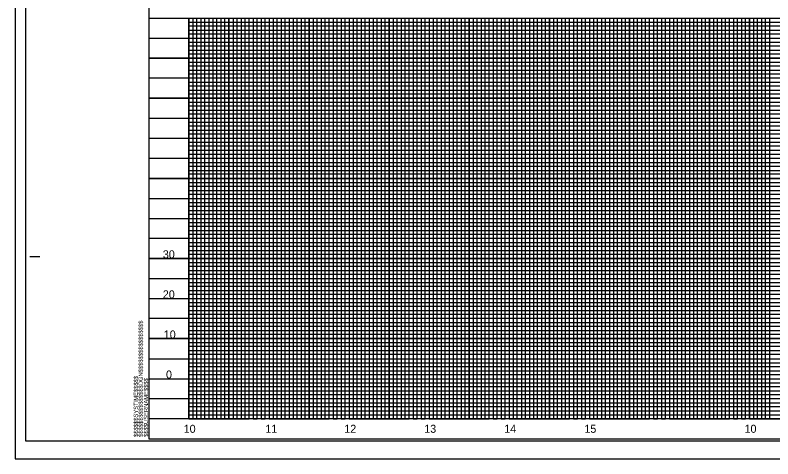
# Model space of a CAD drawing. Extents: x 2180324 to 2182216, y 74532 to 75632.
# Drawn here: x 2180324 to 2181270, y 74532 to 75086 of the extents above; entities that cross this region are included whole.
import ezdxf

# ---------------------------------------------------------------- set-up
doc = ezdxf.new("R2010")
doc.units = 0
for name, color, linetype in [('Exist Structure Minor Culvert Topo', 7, 'Continuous'), ('Old_Level_1', 7, 'Continuous'), ('Old_Level_11', 7, 'Continuous'), ('Old_Level_2', 7, 'Continuous'), ('Old_Level_3', 7, 'Continuous'), ('Scratch_Level_0', 7, 'Continuous'), ('Sheet Border Standard 30in CELL', 7, 'Continuous'), ('Sheet Cutting Line CELL', 7, 'Continuous'), ('Sheet Plot Border Outside CELL', 7, 'Continuous'), ('Sheet Sticker Exception Certification CELL', 7, 'Continuous'), ('Sheet Sticker Incomplete CELL', 7, 'Continuous'), ('Sheet Sticker Preliminary CELL', 7, 'Continuous')]:
    doc.layers.add(name, color=color, linetype=linetype)

msp = doc.modelspace()

# ---------------------------------------------------------------- linework, layer by layer
at = {"layer": 'Exist Structure Minor Culvert Topo'}
for points in [[(2180540.9, 75082.28), (2181240.9, 75082.28), (2181240.9, 74582.28), (2180540.9, 74582.28)], [(2181240.9, 75082.28), (2181940.9, 75082.28), (2181940.9, 74582.28), (2181240.9, 74582.28)]]:
    msp.add_lwpolyline(points, close=True, dxfattribs=at)
at = {"layer": 'Old_Level_11'}
for p, q in [((2180490.9, 75082.28), (2181990.79, 75082.28)), ((2180540.9, 75082.28), (2180540.9, 74582.28)), ((2180590.9, 75082.28), (2180590.9, 74582.28)), ((2180640.9, 75082.28), (2180640.9, 74582.28)), ((2180690.9, 75082.28), (2180690.9, 74582.28)), ((2180740.9, 75082.28), (2180740.9, 74582.28)), ((2180790.9, 75082.28), (2180790.9, 74582.28)), ((2180840.9, 75082.28), (2180840.9, 74582.28)), ((2180890.9, 75082.28), (2180890.9, 74582.28)), ((2180940.9, 75082.28), (2180940.9, 74582.28)), ((2180990.9, 75082.28), (2180990.9, 74582.28)), ((2181040.9, 75082.28), (2181040.9, 74582.28)), ((2181090.9, 75082.28), (2181090.9, 74582.28)), ((2181140.9, 75082.28), (2181140.9, 74582.28)), ((2181190.9, 75082.28), (2181190.9, 74582.28)), ((2181240.9, 75082.28), (2181240.9, 74582.28)), ((2180490.9, 75032.28), (2181990.79, 75032.28)), ((2180490.9, 74982.28), (2181990.79, 74982.28)), ((2180490.9, 74932.28), (2181990.79, 74932.28)), ((2180490.9, 74882.28), (2181990.79, 74882.28)), ((2180490.9, 74832.28), (2181990.79, 74832.28)), ((2180490.9, 74782.28), (2181990.79, 74782.28)), ((2180490.9, 74732.28), (2181990.79, 74732.28)), ((2180490.9, 74682.28), (2181990.79, 74682.28)), ((2180490.9, 74632.28), (2181990.79, 74632.28))]:
    msp.add_line(p, q, dxfattribs=at)
at = {"layer": 'Old_Level_2'}
for points in [[(2180515.9, 75082.28), (2180565.9, 75082.28), (2180565.9, 74582.28), (2180615.9, 74582.28), (2180615.9, 75082.28), (2180665.9, 75082.28), (2180665.9, 74582.28), (2180715.9, 74582.28), (2180715.9, 75082.28), (2180765.9, 75082.28), (2180765.9, 74582.28), (2180815.9, 74582.28), (2180815.9, 75082.28), (2180865.9, 75082.28), (2180865.9, 74582.28), (2180915.9, 74582.28), (2180915.9, 75082.28), (2180965.9, 75082.28), (2180965.9, 74582.28), (2181015.9, 74582.28), (2181015.9, 75082.28), (2181065.9, 75082.28), (2181065.9, 74582.28), (2181115.9, 74582.28), (2181115.9, 74582.28), (2181115.9, 75082.28), (2181165.9, 75082.28), (2181165.9, 74582.28), (2181215.9, 74582.28), (2181215.9, 75082.28), (2181265.9, 75082.28), (2181265.9, 74582.28), (2181315.9, 74582.28)], [(2180490.9, 75057.28), (2181990.9, 75057.28)], [(2181990.9, 75007.28), (2180490.9, 75007.28), (2180490.9, 74957.28), (2181990.9, 74957.28)], [(2181990.9, 74907.28), (2180490.9, 74907.28), (2180490.9, 74857.28), (2181990.9, 74857.28)], [(2181990.9, 74807.28), (2180490.9, 74807.28), (2180490.9, 74757.28), (2181990.9, 74757.28)], [(2181990.9, 74707.28), (2180490.9, 74707.28), (2180490.9, 74657.28), (2181990.9, 74657.28)], [(2181990.9, 74607.28), (2180490.9, 74607.28)]]:
    msp.add_lwpolyline(points, dxfattribs=at)
at = {"layer": 'Scratch_Level_0'}
for p, q in [((2180323.9, 75632.28), (2180323.9, 74532.28)), ((2180323.9, 74532.28), (2182007.9, 74532.28))]:
    msp.add_line(p, q, dxfattribs=at)
at = {"layer": 'Sheet Border Standard 30in CELL'}
msp.add_lwpolyline([(2180540.9, 75082.28), (2181940.9, 75082.28), (2181940.9, 74582.28), (2180540.9, 74582.28)], close=True, dxfattribs=at)
at = {"layer": 'Sheet Cutting Line CELL'}
for p, q in [((2180490.9, 75082.28), (2181990.9, 75082.28)), ((2180342.4, 74784.78), (2180354.9, 74784.78)), ((2181990.9, 74582.28), (2180490.9, 74582.28)), ((2180490.9, 74557.28), (2181990.9, 74557.28)), ((2180490.9, 74557.28), (2180490.9, 74557.28)), ((2180490.9, 74557.28), (2180490.9, 74557.28)), ((2180490.9, 74557.28), (2180490.9, 74557.28)), ((2180490.9, 74557.28), (2180490.9, 74557.28)), ((2180490.9, 74557.28), (2180490.9, 74557.28)), ((2180490.9, 74557.28), (2180490.9, 74557.28)), ((2180490.9, 74557.28), (2180490.9, 74557.28))]:
    msp.add_line(p, q, dxfattribs=at)
msp.add_lwpolyline([(2181990.9, 75607.28), (2180490.9, 75607.28), (2180490.9, 74557.28), (2181990.9, 74557.28)], close=True, dxfattribs=at)
msp.add_lwpolyline([(2180528.4, 74557.28), (2180528.4, 74557.28)], dxfattribs=at)
at = {"layer": 'Sheet Plot Border Outside CELL'}
for p, q in [((2180540.9, 75077.28), (2181940.9, 75077.28)), ((2181940.9, 75072.28), (2180540.9, 75072.28)), ((2180540.9, 75067.28), (2181940.9, 75067.28)), ((2181940.9, 75062.28), (2180540.9, 75062.28)), ((2180540.9, 75052.28), (2181940.9, 75052.28)), ((2181940.9, 75047.28), (2180540.9, 75047.28)), ((2180540.9, 75042.28), (2181940.9, 75042.28)), ((2181940.9, 75037.28), (2180540.9, 75037.28)), ((2180540.9, 75027.28), (2181940.9, 75027.28)), ((2181940.9, 75022.28), (2180540.9, 75022.28)), ((2180540.9, 75017.28), (2181940.9, 75017.28)), ((2181940.9, 75012.28), (2180540.9, 75012.28)), ((2180540.9, 75002.28), (2181940.9, 75002.28)), ((2181940.9, 74997.28), (2180540.9, 74997.28)), ((2180540.9, 74992.28), (2181940.9, 74992.28)), ((2181940.9, 74987.28), (2180540.9, 74987.28)), ((2180540.9, 74977.28), (2181940.9, 74977.28)), ((2181940.9, 74972.28), (2180540.9, 74972.28)), ((2180540.9, 74967.28), (2181940.9, 74967.28)), ((2181940.9, 74962.28), (2180540.9, 74962.28)), ((2180540.9, 74952.28), (2181940.9, 74952.28)), ((2181940.9, 74947.28), (2180540.9, 74947.28)), ((2180540.9, 74942.28), (2181940.9, 74942.28)), ((2181940.9, 74937.28), (2180540.9, 74937.28)), ((2180540.9, 74927.28), (2181940.9, 74927.28)), ((2181940.9, 74922.28), (2180540.9, 74922.28)), ((2180540.9, 74917.28), (2181940.9, 74917.28)), ((2181940.9, 74912.28), (2180540.9, 74912.28)), ((2180540.9, 74902.28), (2181940.9, 74902.28)), ((2181940.9, 74897.28), (2180540.9, 74897.28)), ((2180540.9, 74892.28), (2181940.9, 74892.28)), ((2181940.9, 74887.28), (2180540.9, 74887.43)), ((2180540.9, 74877.28), (2181940.9, 74877.28)), ((2181940.9, 74872.28), (2180540.9, 74872.28)), ((2180540.9, 74867.28), (2181940.9, 74867.28)), ((2181940.9, 74862.28), (2180540.9, 74862.28)), ((2180540.9, 74852.28), (2181940.9, 74852.28)), ((2181940.9, 74847.28), (2180540.9, 74847.28)), ((2180540.9, 74842.28), (2181940.9, 74842.28)), ((2181940.9, 74837.28), (2180540.9, 74837.28)), ((2180540.9, 74827.28), (2181940.9, 74827.28)), ((2181940.9, 74822.28), (2180540.9, 74822.28)), ((2180540.9, 74817.28), (2181940.9, 74817.28)), ((2181940.9, 74812.28), (2180540.9, 74812.28)), ((2180540.9, 74802.28), (2181940.9, 74802.28)), ((2181940.9, 74797.28), (2180540.9, 74797.28)), ((2180540.9, 74792.28), (2181940.9, 74792.28)), ((2181940.9, 74787.28), (2180540.9, 74787.28)), ((2180540.9, 74777.28), (2181940.9, 74777.28)), ((2181940.9, 74772.28), (2180540.9, 74772.28)), ((2180540.9, 74767.28), (2181940.9, 74767.28)), ((2181940.9, 74762.28), (2180540.9, 74762.28)), ((2180540.9, 74752.28), (2181940.9, 74752.28)), ((2181940.9, 74747.28), (2180540.9, 74747.28)), ((2180540.9, 74742.28), (2181940.9, 74742.28)), ((2181940.9, 74737.28), (2180540.9, 74737.28)), ((2180540.9, 74727.28), (2181940.9, 74727.28)), ((2181940.9, 74722.28), (2180540.9, 74722.28)), ((2180540.9, 74717.28), (2181940.9, 74717.28)), ((2181940.9, 74712.28), (2180540.9, 74712.28)), ((2180540.9, 74702.28), (2181940.9, 74702.28)), ((2181940.9, 74697.28), (2180540.9, 74697.28)), ((2180540.9, 74692.28), (2181940.9, 74692.28)), ((2181940.9, 74687.28), (2180540.9, 74687.28)), ((2180540.9, 74677.28), (2181940.9, 74677.28)), ((2181940.9, 74672.28), (2180540.9, 74672.28)), ((2180540.9, 74667.28), (2181940.9, 74667.28)), ((2181940.9, 74662.28), (2180540.9, 74662.28)), ((2180540.9, 74652.28), (2181940.9, 74652.28)), ((2181940.9, 74647.28), (2180540.9, 74647.28)), ((2180540.9, 74642.28), (2181940.9, 74642.28)), ((2181940.9, 74637.28), (2180540.9, 74637.28)), ((2180540.9, 74627.28), (2181940.9, 74627.28)), ((2181940.9, 74622.28), (2180540.9, 74622.28)), ((2180540.9, 74617.28), (2181940.9, 74617.28)), ((2181940.9, 74612.28), (2180540.9, 74612.28)), ((2180540.9, 74602.28), (2181940.9, 74602.28)), ((2181940.9, 74597.28), (2180540.9, 74597.28)), ((2180540.9, 74592.28), (2181940.9, 74592.28)), ((2180540.9, 74587.28), (2181940.9, 74587.28))]:
    msp.add_line(p, q, dxfattribs=at)
for points in [[(2180540.9, 75082.28), (2180545.9, 75082.28), (2180545.9, 74582.28), (2180550.9, 74582.28), (2180550.9, 75082.28), (2180555.9, 75082.28), (2180555.9, 74582.28), (2180560.9, 74582.28), (2180560.9, 75082.28), (2180570.9, 75082.28), (2180570.9, 74582.28), (2180575.9, 74582.28), (2180575.9, 75082.28), (2180580.9, 75082.28), (2180580.9, 74582.28), (2180585.9, 74582.28), (2180595.9, 74582.28), (2180600.9, 74582.28), (2180600.9, 75082.28), (2180605.9, 75082.28), (2180605.9, 74582.28), (2180610.9, 74582.28), (2180610.9, 75082.28), (2180620.9, 75082.28), (2180620.9, 74582.28), (2180625.9, 74582.28), (2180625.9, 75082.28), (2180630.9, 75082.28), (2180630.9, 74582.28), (2180635.9, 74582.28), (2180635.9, 75082.28), (2180645.9, 75082.28), (2180645.9, 74582.28), (2180650.9, 74582.28), (2180650.9, 75082.28), (2180655.9, 75082.28), (2180655.9, 74582.28), (2180660.9, 74582.28), (2180660.9, 75082.28), (2180670.9, 75082.28), (2180670.9, 74582.28), (2180675.9, 74582.28), (2180675.9, 75082.28), (2180680.9, 75082.28), (2180680.9, 74582.28), (2180685.9, 74582.28), (2180685.9, 75082.28), (2180695.9, 75082.28), (2180695.9, 74582.28), (2180700.9, 74582.28), (2180700.9, 75082.28), (2180705.9, 75082.28), (2180705.9, 74582.28), (2180710.9, 74582.28), (2180710.9, 75082.28), (2180720.9, 75082.28), (2180720.9, 74582.28), (2180725.9, 74582.28), (2180725.9, 75082.28), (2180730.9, 75082.28), (2180730.9, 74582.28), (2180735.9, 74582.28), (2180735.9, 75082.28), (2180745.9, 75082.28), (2180745.9, 74582.28), (2180750.9, 74582.28), (2180750.9, 75082.28), (2180755.9, 75082.28), (2180755.9, 74582.28)], [(2180585.9, 74582.28), (2180585.9, 75082.28), (2180595.9, 75082.28), (2180595.9, 74582.28)], [(2180755.9, 74582.28), (2180760.9, 74582.28), (2180760.9, 75082.28), (2180770.9, 75082.28), (2180770.9, 74582.28), (2180775.9, 74582.28), (2180775.9, 75082.28), (2180780.9, 75082.28), (2180780.9, 74582.28), (2180785.9, 74582.28), (2180785.9, 75082.28), (2180795.9, 75082.28), (2180795.9, 74582.28), (2180800.9, 74582.28), (2180800.9, 75082.28), (2180805.9, 75082.28), (2180805.9, 74582.28), (2180810.9, 74582.28), (2180810.9, 75082.28), (2180820.9, 75082.28), (2180820.9, 74582.28), (2180825.9, 74582.28), (2180825.9, 75082.28), (2180830.9, 75082.28), (2180830.9, 74582.28), (2180835.9, 74582.28), (2180835.9, 75082.28), (2180845.9, 75082.28), (2180845.9, 74582.28), (2180850.9, 74582.28), (2180850.9, 75082.28), (2180855.9, 75082.28), (2180855.9, 74582.28), (2180860.9, 74582.28), (2180860.9, 75082.28), (2180870.9, 75082.28), (2180870.9, 74582.28), (2180875.9, 74582.28), (2180875.9, 75082.28), (2180880.9, 75082.28), (2180880.9, 74582.28), (2180885.9, 74582.28), (2180885.9, 75082.28), (2180895.9, 75082.28), (2180895.9, 74582.28), (2180900.9, 74582.28), (2180900.9, 75082.28), (2180905.9, 75082.28), (2180905.9, 74582.28), (2180910.9, 74582.28), (2180910.9, 75082.28), (2180920.9, 75082.28), (2180920.9, 74582.28), (2180925.9, 74582.28), (2180925.9, 75082.28), (2180930.9, 75082.28), (2180930.9, 74582.28), (2180935.9, 74582.28), (2180935.9, 75082.28), (2180945.9, 75082.28), (2180945.9, 74582.28), (2180950.9, 74582.28), (2180950.9, 75082.28), (2180955.9, 75082.28), (2180955.9, 74582.28), (2180960.9, 74582.28), (2180960.9, 75082.28), (2180970.9, 75082.28), (2180970.9, 74582.28), (2180975.9, 74582.28), (2180975.9, 75082.28), (2180980.9, 75082.28), (2180980.9, 74582.28), (2180985.9, 74582.28), (2180985.9, 75082.28), (2180995.9, 75082.28), (2180995.9, 74582.28), (2181000.9, 74582.28), (2181000.9, 75082.28), (2181005.9, 75082.28), (2181005.9, 74582.28), (2181010.9, 74582.28), (2181010.9, 75082.28), (2181020.9, 75082.28), (2181020.9, 74582.28), (2181025.9, 74582.28), (2181025.9, 75082.28), (2181030.9, 75082.28), (2181030.9, 74582.28), (2181035.9, 74582.28), (2181035.9, 75082.28), (2181045.9, 75082.28), (2181045.9, 74582.28), (2181050.9, 74582.28), (2181050.9, 75082.28), (2181055.9, 75082.28), (2181055.9, 74582.28), (2181060.9, 74582.28), (2181060.9, 75082.28), (2181070.9, 75082.28)], [(2181070.9, 75082.28), (2181070.9, 74582.28), (2181075.9, 74582.28), (2181075.9, 75082.28), (2181080.9, 75082.28), (2181080.9, 74582.28), (2181085.9, 74582.28), (2181085.9, 75082.28), (2181095.9, 75082.28), (2181095.9, 74582.28), (2181100.9, 74582.28), (2181100.9, 75082.28), (2181105.9, 75082.28), (2181105.9, 74582.28), (2181110.9, 74582.28), (2181110.9, 75082.28), (2181120.9, 75082.28), (2181120.9, 74582.28), (2181125.9, 74582.28), (2181125.9, 75082.28), (2181130.9, 75082.28), (2181130.9, 74582.28), (2181135.9, 74582.28), (2181135.9, 75082.28), (2181145.9, 75082.28), (2181145.9, 74582.28), (2181150.9, 74582.28), (2181150.9, 75082.28), (2181155.9, 75082.28), (2181155.9, 74582.28), (2181160.9, 74582.28), (2181160.9, 75082.28), (2181170.9, 75082.28), (2181170.9, 74582.28), (2181175.9, 74582.28), (2181175.9, 75082.28), (2181180.9, 75082.28), (2181180.9, 74582.28), (2181185.9, 74582.28), (2181185.9, 75082.28), (2181195.9, 75082.28), (2181195.9, 74582.28), (2181195.9, 74582.28), (2181200.9, 74582.28), (2181200.9, 75082.28), (2181205.9, 75082.28), (2181205.9, 74582.28), (2181210.9, 74582.28), (2181210.9, 75082.28), (2181220.9, 75082.28), (2181220.9, 74582.28), (2181225.9, 74582.28), (2181225.9, 75082.28), (2181230.9, 75082.28), (2181230.9, 74582.28), (2181235.9, 74582.28), (2181235.9, 75082.28), (2181245.9, 75082.28), (2181245.9, 74582.28), (2181250.9, 74582.28), (2181250.9, 75082.28), (2181255.9, 75082.28), (2181255.9, 74582.28), (2181260.9, 74582.28), (2181260.9, 75082.28), (2181270.9, 75082.28)]]:
    msp.add_lwpolyline(points, dxfattribs=at)
at = {"layer": 'Sheet Sticker Exception Certification CELL'}
for p, q in [((2180990.9, 75082.28), (2181040.9, 75082.28)), ((2181090.9, 75082.28), (2181140.9, 75082.28)), ((2181190.9, 75082.28), (2181240.9, 75082.28)), ((2180490.9, 74582.28), (2180490.9, 74582.28))]:
    msp.add_line(p, q, dxfattribs=at)
for points in [[(2180540.9, 75082.28), (2180540.9, 74582.28), (2180590.9, 74582.28), (2180590.9, 75082.28), (2180640.9, 75082.28), (2180640.9, 74582.28), (2180690.9, 74582.28), (2180690.9, 75082.28), (2180740.9, 75082.28), (2180740.9, 74582.28), (2180790.9, 74582.28), (2180790.9, 75082.28), (2180840.9, 75082.28), (2180840.9, 74582.28), (2180890.9, 74582.28), (2180890.9, 75082.28), (2180940.9, 75082.28), (2180940.9, 74582.28), (2180990.9, 74582.28), (2180990.9, 75082.28), (2181040.9, 75082.28), (2181040.9, 74582.28), (2181090.9, 74582.28), (2181090.9, 75082.28), (2181140.9, 75082.28), (2181140.9, 74582.28), (2181190.9, 74582.28), (2181190.9, 75082.28), (2181240.9, 75082.28), (2181240.9, 74582.28), (2181290.9, 74582.28)], [(2181990.9, 75032.28), (2180490.9, 75032.28)], [(2181990.9, 74982.28), (2180490.9, 74982.28), (2180490.9, 74932.28), (2181990.9, 74932.28)], [(2181990.9, 74882.28), (2180490.9, 74882.28), (2180490.9, 74832.28), (2181990.9, 74832.28)], [(2181990.9, 74782.28), (2180490.9, 74782.28), (2180490.9, 74732.28), (2181990.9, 74732.28)], [(2181990.9, 74682.28), (2180490.9, 74682.28), (2180490.9, 74682.28), (2180490.9, 74632.28), (2181990.9, 74632.28)], [(2181990.9, 74582.28), (2180490.9, 74582.28)]]:
    msp.add_lwpolyline(points, dxfattribs=at)
at = {"layer": 'Sheet Sticker Incomplete CELL'}
msp.add_lwpolyline([(2180323.9, 74532.28), (2182007.9, 74532.28), (2182007.9, 75632.28), (2180323.9, 75632.28)], close=True, dxfattribs=at)
at = {"layer": 'Sheet Sticker Preliminary CELL'}
msp.add_lwpolyline([(2180336.9, 74554.73), (2182003.4, 74554.73), (2182003.4, 75609.83), (2180336.9, 75609.83)], close=True, dxfattribs=at)

# ---------------------------------------------------------------- texts
at = {"layer": 'Old_Level_1'}
for s, p in [('10', (2180534.35, 74564.78)), ('11', (2180636.33, 74564.78)), ('12', (2180734.87, 74564.78)), ('13', (2180834.71, 74564.78)), ('14', (2180934.55, 74564.78)), ('15', (2181034.64, 74564.78)), ('10', (2181234.6, 74564.78))]:
    msp.add_text(s, height=10, dxfattribs=at).set_placement(p)
at = {"layer": 'Old_Level_3'}
for s, p in [('30', (2180508.29, 74782.53)), ('30', (2180508.29, 74782.53)), ('30', (2180508.29, 74782.53)), ('20', (2180508.29, 74732.53)), ('20', (2180508.29, 74732.53)), ('20', (2180508.29, 74732.53)), ('10', (2180509.49, 74682.53)), ('10', (2180509.49, 74682.53)), ('10', (2180509.49, 74682.53)), ('0', (2180512.24, 74632.53)), ('0', (2180512.24, 74632.53)), ('0', (2180512.24, 74632.53))]:
    msp.add_text(s, height=10, dxfattribs=at).set_placement(p)
at = {"layer": 'Sheet Cutting Line CELL'}
for s, p in [('$$$$$$$$$$$$$$$$DGN$$$$$$$$$$$$$$$$', (2180483.27, 74559.66)), ('$$$$$$SYSTIME$$$$$', (2180477.22, 74559.66)), ('$$$$USERNAME$$$$', (2180489.84, 74559.67))]:
    msp.add_text(s, height=5.25, rotation=90, dxfattribs=at).set_placement(p)

doc.saveas('drawing.dxf')
